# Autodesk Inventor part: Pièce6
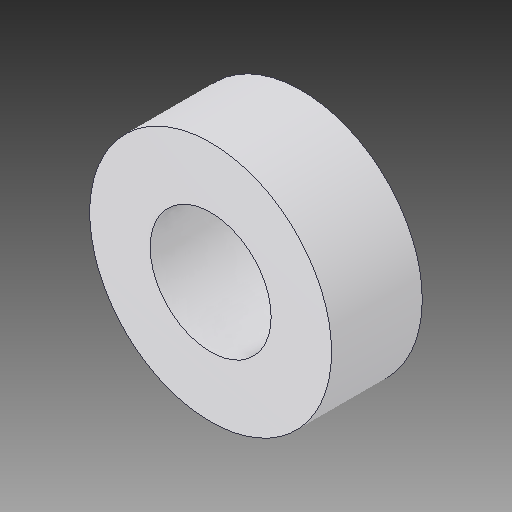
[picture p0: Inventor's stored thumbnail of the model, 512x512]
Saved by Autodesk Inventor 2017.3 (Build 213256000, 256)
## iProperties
Created: 2007-11
Part Number: Pièce6
Material: solidworks materials|Alliage 7079|22
Document SubType Name: Modeling
Designer: ficho
Density: 2.7 g/cm^3
Appearance: 227,227,233
Author: ficho
Sending System: SolidWorks 2009
Last Author: christophe
Last Saved: 2011-01-17
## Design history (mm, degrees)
extrude "Extrusion1"
node "Solide1"
